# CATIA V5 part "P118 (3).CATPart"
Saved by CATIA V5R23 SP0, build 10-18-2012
Part number: 05-LICP-T02-E-S13-P118 (3)
Definition: butee a aiguilles
Description: butee_a_aiguilles_ax_19_32_03
Bounding box of the stored display mesh (mm): x 0.202 to 2.5, y -15.993 to 15.993, z -15.993 to 15.993
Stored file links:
  C:\wamp\www\COURS\CONCEPTION GMP1\TITRE 02-SEMESTRE 2\03-TP7-PRESSE MECANIQUE\eleve\P118 (3).CATPart
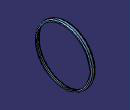
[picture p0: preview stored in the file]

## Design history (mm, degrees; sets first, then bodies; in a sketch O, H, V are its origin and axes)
Body1 (main body)
  Solid1: solid without history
